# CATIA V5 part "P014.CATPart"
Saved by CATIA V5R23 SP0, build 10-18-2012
Part number: 05-LICP-T02-E-S05-P014
Definition: Arbre came moteur
Description: Arbre came moteur
Bounding box of the stored display mesh (mm): x -58 to 120, y -17.954 to 17.954, z -17.954 to 17.954
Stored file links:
  C:\wamp\www\COURS\CONCEPTION GMP1\TITRE 02-SEMESTRE 2\03-TP7-PRESSE MECANIQUE\eleve\P014.CATPart
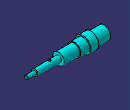
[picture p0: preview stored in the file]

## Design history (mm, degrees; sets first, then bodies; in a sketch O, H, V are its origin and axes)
Body1 (main body)
  Sketch1 on zx-plane, origin (0, 0, 0), H (-1, 0, 0), V (0, 0, 1)
    axis line L1 (71.2642, 0) -> (-60.5013, 0)
    point P1 (71.2642, 0)
    point P3 (58, 0)
    line L2 (58, 0) -> (58, 15)
    line L3 (58, 15) -> (28, 15)
    line L4 (28, 15) -> (28, 18)
    line L5 (28, 18) -> (10, 18)
    line L6 (10, 18) -> (10, 15)
    line L7 (10, 15) -> (-10, 15)
    line L8 (-10, 15) -> (-10, 13)
    line L9 (-10, 13) -> (-46, 13)
    line L10 (-46, 13) -> (-46, 7)
    line L11 (-46, 7) -> (-100, 7)
    line L12 (-100, 7) -> (-100, 4)
    line L13 (-100, 4) -> (-120, 4)
    line L14 (-120, 4) -> (-120, 0)
    point P16 (-120, 0)
    line L15 (-120, 0) -> (58, 0)
    reference intersected line E1 through (0, 0) direction (0, -1) from yz-plane
    distance L8 E1 = 10
    length L7 = 20
    length L5 = 18
    length L3 = 30
    radius about axis L3 L1 = 15
    radius about axis L5 L1 = 18
    radius about axis L7 L1 = 15
    length L9 = 36
    length L11 = 54
    length L13 = 20
    radius about axis L11 L1 = 7
    radius about axis L13 L1 = 4
    distance L9 H = 13
    coincidence: P1 H, P3 L1, P16 H
    horizontal: L1 H, L3 H, L5 H, L7 H, L9 H, L11 H, L13 H, L15 H
    vertical: L2 V, L4 V, L6 V, L8 V, L10 V, L12 V, L14 V
  Shaft1: profile Sketch1, axis Sketch1.L1, angle 360
  Sketch2 on face of Shaft1, origin (-58, 0, 0), H (0, 1, 0), V (0, 0, -1)
    point P1 (0, 0)
  Hole1: placed by Sketch2, at (-58, 0, 0) direction (1, 0, 0), diameter 18, depth 42, V-bottom angle 120
  Sketch3 on xy-plane, origin (0, 0, 0), H (1, 0, 0), V (0, 1, 0)
    line L1 (-26, 12) -> (-22, 12)
    line L2 (-22, 12) -> (-22, 0)
    line L3 (-22, 0) -> (-26, 0)
    line L4 (-26, 0) -> (-26, 12)
    reference projected line E1 (-58, -15) -> (-58, 15) from edge [face of Shaft1 | face of Shaft1]
    length L1 = 4
    distance L3 L1 = 12
    distance L4 E1 = 32
    horizontal: L1 H, L3 H
    vertical: L2 V, L4 V
    coincidence: L3 H
  Groove1: profile Sketch3, axis Sketch3.H, angle 360
  Thread1: "M8", diameter 8, depth 18, pitch 1.25, on face of Shaft1, from face of Shaft1
  Chamfer1: length 1, angle 45, on edge [face of Shaft1 | face of Shaft1]
  Sketch4 on xy-plane, origin (0, 0, 0), H (1, 0, 0), V (0, 1, 0)
    circle A1 centre (66, 0) radius 2.5
    point P1 (66, 0)
    reference intersected line E1 through (0, 0) direction (0, 1) from yz-plane
    radius A1 = 2.5
    distance P1 E1 = 66
    coincidence: P1 H
  Pocket1: profile Sketch4, direction (0, 0, -1), through (limit type 3), opposite side through (limit type 3)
